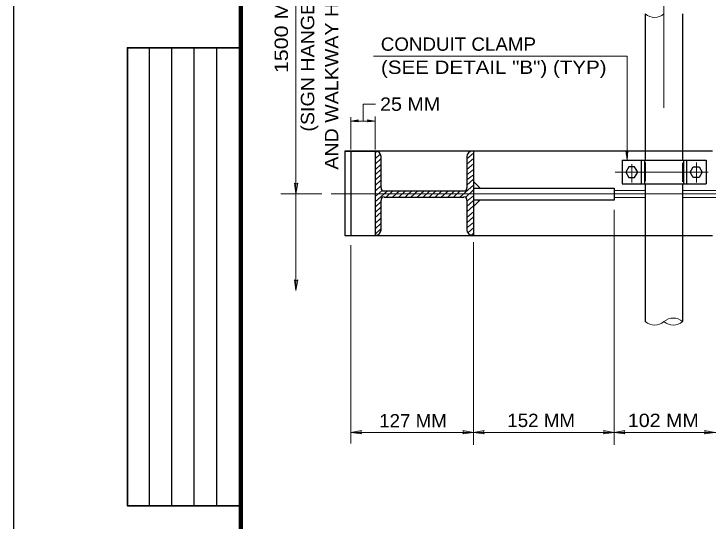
# Model space of a CAD drawing. Extents: x 312601.858 to 312602.699, y 144420.109 to 144420.704.
# Drawn here: x 312601.8578 to 312602.0138, y 144420.2326 to 144420.3467 of the extents above; entities that cross this region are included whole.
import ezdxf
from ezdxf.enums import TextEntityAlignment as Align

# ---------------------------------------------------------------- set-up
doc = ezdxf.new("R2010")
doc.units = 0
doc.header["$LTSCALE"] = 0.0012
for name, pattern in [('DOT_DASHED', [7.7, 5, -1.2, 0.3, -1.2]), ('LONG_DASHED', [7.5, 6, -1.5]), ('MEDIUM_DASHED', [4.5, 3, -1.5])]:
    doc.linetypes.add(name, pattern=pattern)
for name, color, linetype, lineweight in [('1', 7, 'Continuous', 13), ('2', 7, 'Continuous', 13), ('39', 7, 'Continuous', 13), ('60', 7, 'Continuous', 25)]:
    doc.layers.add(name, color=color, linetype=linetype, lineweight=lineweight)

msp = doc.modelspace()

# ---------------------------------------------------------------- hatches: boundary and pattern name
at = {"layer": '39'}
for points in [[(312601.9351, 144420.3226), (312601.9352, 144420.3224), (312601.9335, 144420.3226), (312601.9352, 144420.3229)], [(312601.9375, 144420.3226), (312601.9373, 144420.3229), (312601.939, 144420.3226), (312601.9373, 144420.3224)], [(312601.9212, 144420.3084), (312601.9216, 144420.3086), (312601.9212, 144420.3062), (312601.9209, 144420.3086)], [(312601.9212, 144420.2867), (312601.9216, 144420.2869), (312601.9212, 144420.2845), (312601.9209, 144420.2869)], [(312601.9357, 144420.2526), (312601.9359, 144420.2523), (312601.9335, 144420.2526), (312601.9359, 144420.253)], [(312601.9589, 144420.2526), (312601.9587, 144420.253), (312601.9611, 144420.2526), (312601.9587, 144420.2523)], [(312601.9633, 144420.2526), (312601.9635, 144420.2523), (312601.9611, 144420.2526), (312601.9635, 144420.253)], [(312601.9905, 144420.2526), (312601.9903, 144420.253), (312601.9927, 144420.2526), (312601.9903, 144420.2523)], [(312601.9949, 144420.2526), (312601.9951, 144420.2523), (312601.9927, 144420.2526), (312601.9951, 144420.253)], [(312602.0132, 144420.2526), (312602.013, 144420.253), (312602.0154, 144420.2526), (312602.013, 144420.2523)]]:
    msp.add_hatch(color=256, dxfattribs=at).paths.add_polyline_path(points)

# ---------------------------------------------------------------- linework, layer by layer
at = {"layer": '1', "linetype": 'DOT_DASHED'}
for p, q in [((312602.0039, 144420.4256), (312602.0039, 144420.2754)), ((312602.0112, 144420.3133), (312602.0112, 144420.3088)), ((312601.9967, 144420.3129), (312601.9967, 144420.3088)), ((312601.9929, 144420.3111), (312602.0138, 144420.3111)), ((312601.9291, 144420.3062), (312602.114, 144420.3062))]:
    msp.add_line(p, q, dxfattribs=at)
at = {"layer": '1', "lineweight": 25}
for p, q in [((312601.9997, 144420.3467), (312601.9997, 144420.3138)), ((312602.0081, 144420.3467), (312602.0081, 144420.3138)), ((312601.9322, 144420.3158), (312601.9322, 144420.2969)), ((312601.9322, 144420.3158), (312601.9391, 144420.3158)), ((312601.9997, 144420.3158), (312601.9322, 144420.3158)), ((312601.9335, 144420.3158), (312601.9335, 144420.2969)), ((312601.939, 144420.3158), (312601.939, 144420.2969)), ((312601.9611, 144420.3158), (312601.9611, 144420.2969)), ((312602.0148, 144420.3158), (312602.0081, 144420.3158)), ((312601.9403, 144420.3146), (312601.9403, 144420.3076)), ((312601.9596, 144420.3146), (312601.9596, 144420.3076)), ((312601.9945, 144420.3138), (312602.0134, 144420.3138)), ((312601.9988, 144420.3138), (312601.9988, 144420.3085)), ((312601.9995, 144420.3138), (312601.9995, 144420.3085)), ((312602.0083, 144420.3138), (312602.0083, 144420.3085)), ((312602.009, 144420.3138), (312602.009, 144420.3085)), ((312602.0134, 144420.3138), (312602.0134, 144420.3085)), ((312601.9997, 144420.3085), (312601.9997, 144420.2775)), ((312602.0081, 144420.3085), (312602.0081, 144420.2775)), ((312601.941, 144420.3069), (312601.9589, 144420.3069)), ((312601.9611, 144420.3075), (312601.9927, 144420.3075)), ((312601.9927, 144420.3075), (312601.9927, 144420.3048)), ((312601.941, 144420.3055), (312601.9589, 144420.3055)), ((312601.9403, 144420.3048), (312601.9403, 144420.2981)), ((312601.9596, 144420.3048), (312601.9596, 144420.2981)), ((312601.9611, 144420.3049), (312601.9927, 144420.3049)), ((312601.9322, 144420.2969), (312601.9391, 144420.2969)), ((312601.939, 144420.2969), (312601.9997, 144420.2969)), ((312602.0081, 144420.2969), (312602.0148, 144420.2969))]:
    msp.add_line(p, q, dxfattribs=at)
at = {"layer": '1'}
for p, q in [((312601.9335, 144420.3235), (312601.9335, 144420.3162)), ((312601.9335, 144420.3226), (312601.939, 144420.3226)), ((312601.939, 144420.3236), (312601.939, 144420.3162)), ((312601.939, 144420.3154), (312601.9394, 144420.3158)), ((312601.939, 144420.3141), (312601.9402, 144420.3152)), ((312601.9596, 144420.3141), (312601.9611, 144420.3154)), ((312601.939, 144420.3129), (312601.9403, 144420.3141)), ((312601.9596, 144420.3129), (312601.9611, 144420.3142)), ((312601.939, 144420.3116), (312601.9403, 144420.3128)), ((312601.939, 144420.3105), (312601.9403, 144420.3117)), ((312601.9596, 144420.3117), (312601.9611, 144420.313)), ((312601.9596, 144420.3105), (312601.9611, 144420.3117)), ((312601.939, 144420.3093), (312601.9403, 144420.3105)), ((312601.9596, 144420.3094), (312601.9611, 144420.3105)), ((312601.939, 144420.3081), (312601.9403, 144420.3093)), ((312601.9596, 144420.3082), (312601.9611, 144420.3095)), ((312601.939, 144420.3068), (312601.9403, 144420.308)), ((312601.939, 144420.3056), (312601.9406, 144420.307)), ((312601.939, 144420.3044), (312601.9418, 144420.3069)), ((312601.9415, 144420.3067), (312601.9417, 144420.3069)), ((312601.9415, 144420.3055), (312601.943, 144420.3069)), ((312601.9429, 144420.3055), (312601.9445, 144420.3069)), ((312601.9443, 144420.3055), (312601.9458, 144420.3069)), ((312601.9457, 144420.3055), (312601.9472, 144420.3069)), ((312601.947, 144420.3055), (312601.9486, 144420.3069)), ((312601.9484, 144420.3055), (312601.95, 144420.3069)), ((312601.9498, 144420.3055), (312601.9513, 144420.3069)), ((312601.9511, 144420.3055), (312601.9526, 144420.3069)), ((312601.9525, 144420.3055), (312601.954, 144420.3069)), ((312601.9538, 144420.3055), (312601.9555, 144420.3069)), ((312601.9553, 144420.3055), (312601.9568, 144420.3069)), ((312601.9566, 144420.3055), (312601.9581, 144420.3069)), ((312601.958, 144420.3055), (312601.9611, 144420.3082)), ((312601.9593, 144420.3054), (312601.9611, 144420.3071)), ((312601.9178, 144420.3062), (312601.927, 144420.3062)), ((312601.9212, 144420.3062), (312601.9212, 144420.2845)), ((312601.9457, 144420.3055), (312601.9466, 144420.3064)), ((312601.9596, 144420.3046), (312601.9611, 144420.3058)), ((312601.939, 144420.3032), (312601.9403, 144420.3044)), ((312601.9596, 144420.3034), (312601.9611, 144420.3047)), ((312601.939, 144420.302), (312601.9403, 144420.3032)), ((312601.9596, 144420.3022), (312601.9611, 144420.3035)), ((312601.9927, 144420.3026), (312601.9927, 144420.2498)), ((312601.939, 144420.3009), (312601.9403, 144420.302)), ((312601.939, 144420.2996), (312601.9403, 144420.3008)), ((312601.9596, 144420.3009), (312601.9611, 144420.3022)), ((312601.9596, 144420.2997), (312601.9611, 144420.3011)), ((312601.939, 144420.2984), (312601.9403, 144420.2996)), ((312601.9596, 144420.2986), (312601.9611, 144420.2998)), ((312601.939, 144420.2972), (312601.9403, 144420.2984)), ((312601.9598, 144420.2975), (312601.9611, 144420.2986)), ((312601.9606, 144420.2969), (312601.9611, 144420.2974)), ((312601.9335, 144420.2947), (312601.9335, 144420.2501)), ((312601.9611, 144420.2954), (312601.9611, 144420.2498))]:
    msp.add_line(p, q, dxfattribs=at)
at = {"layer": '1', "linetype": 'LONG_DASHED', "lineweight": 25}
for p, q in [((312602.0081, 144420.3158), (312601.9997, 144420.3158)), ((312601.9997, 144420.2969), (312602.0081, 144420.2969))]:
    msp.add_line(p, q, dxfattribs=at)
at = {"layer": '1', "linetype": 'MEDIUM_DASHED', "lineweight": 25}
for p, q in [((312601.9997, 144420.3133), (312601.9997, 144420.3091)), ((312602.0081, 144420.3132), (312602.0081, 144420.3089))]:
    msp.add_line(p, q, dxfattribs=at)
at = {"layer": '1', "linetype": 'LONG_DASHED'}
for p, q in [((312601.9927, 144420.307), (312601.9997, 144420.307)), ((312602.0081, 144420.307), (312602.042, 144420.307)), ((312601.9927, 144420.3054), (312601.9997, 144420.3054)), ((312602.0081, 144420.3054), (312602.042, 144420.3054))]:
    msp.add_line(p, q, dxfattribs=at)
at = {"layer": '1'}
for points in [[(312601.9212, 144420.4129), (312601.9212, 144420.3925), (312601.9212, 144420.3062)], [(312601.9386, 144420.3372), (312601.9956, 144420.3372), (312601.9956, 144420.3139)], [(312601.9335, 144420.2526), (312601.9611, 144420.2526), (312601.9927, 144420.2526), (312602.0154, 144420.2526), (312602.0985, 144420.2526)]]:
    msp.add_lwpolyline(points, dxfattribs=at)
msp.add_lwpolyline([(312601.9958, 144420.3159), (312601.9956, 144420.3139), (312601.9953, 144420.3159), (312601.9956, 144420.3156)], close=True, dxfattribs=at)
at = {"layer": '1', "lineweight": 25}
msp.add_lwpolyline([(312601.9945, 144420.3138), (312601.9945, 144420.3085), (312602.0134, 144420.3085)], dxfattribs=at)
for points in [[(312601.996, 144420.3099), (312601.9973, 144420.3099), (312601.998, 144420.3111), (312601.9973, 144420.3123), (312601.996, 144420.3123), (312601.9953, 144420.3111)], [(312602.0118, 144420.3099), (312602.0105, 144420.3099), (312602.0098, 144420.3111), (312602.0105, 144420.3123), (312602.0118, 144420.3123), (312602.0125, 144420.3111)]]:
    msp.add_lwpolyline(points, close=True, dxfattribs=at)
at = {"layer": '1'}
for centre, radius, start, end in [((312602.0018, 144420.349056), 0.003156, 228.29108, 311.70892), ((312602.0018, 144420.349056), 0.003156, 228.29108, 311.70892), ((312602.0018, 144420.349056), 0.003156, 228.29108, 311.70892), ((312601.958935, 144420.307565), 0.00068, 359.62724, 0), ((312602.0018, 144420.279856), 0.003156, 228.29108, 311.70892), ((312602.0018, 144420.279856), 0.003156, 228.29108, 311.70892), ((312602.0018, 144420.279856), 0.003156, 228.29108, 311.70892), ((312602.006, 144420.275144), 0.003156, 48.29108, 131.70892), ((312602.006, 144420.275144), 0.003156, 48.29108, 131.70892), ((312602.006, 144420.275144), 0.003156, 48.29108, 131.70892), ((312602.006, 144420.279856), 0.003156, 228.29108, 311.70892), ((312602.006, 144420.279856), 0.003156, 228.29108, 311.70892), ((312602.006, 144420.279856), 0.003156, 228.29108, 311.70892)]:
    msp.add_arc(centre, radius, start, end, dxfattribs=at)
at = {"layer": '1', "lineweight": 25}
for centre, radius, start, end in [((312601.93913, 144420.31462), 0.00119, 0, 90), ((312601.960805, 144420.31462), 0.00119, 90, 180), ((312601.941, 144420.307565), 0.00068, 180, 270), ((312601.958935, 144420.307565), 0.00068, 270, 0), ((312601.941, 144420.304845), 0.00068, 90, 180), ((312601.958935, 144420.304845), 0.00068, 0, 90), ((312601.93913, 144420.29813), 0.00119, 270, 0), ((312601.960805, 144420.29813), 0.00119, 180, 270)]:
    msp.add_arc(centre, radius, start, end, dxfattribs=at)
at = {"layer": '2'}
for p in [(312601.9363, 144420.3226), (312601.9391, 144420.3264)]:
    msp.add_line(p, (312601.9363, 144420.3264), dxfattribs=at)
for points in [[(312601.9611, 144420.3075), (312601.9626, 144420.3075), (312601.9611, 144420.309)], [(312601.9611, 144420.3049), (312601.9626, 144420.3049), (312601.9611, 144420.3034)]]:
    msp.add_lwpolyline(points, close=True, dxfattribs=at)
at = {"layer": '39', "lineweight": 25}
msp.add_line((312601.8578, 144420.1095), (312601.8578, 144420.7035), dxfattribs=at)
at = {"layer": '39', "lineweight": 158}
msp.add_lwpolyline([(312601.9088, 144420.1247), (312601.9088, 144420.6645), (312602.6838, 144420.6645)], dxfattribs=at)
at = {"layer": '39'}
for points in [[(312601.9351, 144420.3226), (312601.9352, 144420.3224), (312601.9335, 144420.3226), (312601.9352, 144420.3229)], [(312601.9375, 144420.3226), (312601.9373, 144420.3229), (312601.939, 144420.3226), (312601.9373, 144420.3224)], [(312601.9212, 144420.3084), (312601.9216, 144420.3086), (312601.9212, 144420.3062), (312601.9209, 144420.3086)], [(312601.9212, 144420.2867), (312601.9216, 144420.2869), (312601.9212, 144420.2845), (312601.9209, 144420.2869)], [(312601.9357, 144420.2526), (312601.9359, 144420.2523), (312601.9335, 144420.2526), (312601.9359, 144420.253)], [(312601.9589, 144420.2526), (312601.9587, 144420.253), (312601.9611, 144420.2526), (312601.9587, 144420.2523)], [(312601.9633, 144420.2526), (312601.9635, 144420.2523), (312601.9611, 144420.2526), (312601.9635, 144420.253)], [(312601.9905, 144420.2526), (312601.9903, 144420.253), (312601.9927, 144420.2526), (312601.9903, 144420.2523)], [(312601.9949, 144420.2526), (312601.9951, 144420.2523), (312601.9927, 144420.2526), (312601.9951, 144420.253)], [(312602.0132, 144420.2526), (312602.013, 144420.253), (312602.0154, 144420.2526), (312602.013, 144420.2523)]]:
    msp.add_lwpolyline(points, close=True, dxfattribs=at)
at = {"layer": '60'}
for p, q in [((312601.8883, 144420.2361), (312601.8883, 144420.3391)), ((312601.8933, 144420.2361), (312601.8933, 144420.3391)), ((312601.8983, 144420.2361), (312601.8983, 144420.3391)), ((312601.9034, 144420.2361), (312601.9034, 144420.3391))]:
    msp.add_line(p, q, dxfattribs=at)
at = {"layer": '60', "lineweight": 35}
msp.add_lwpolyline([(312601.9084, 144420.2361), (312601.8833, 144420.2361), (312601.8833, 144420.3391), (312601.9084, 144420.3391)], dxfattribs=at)

# ---------------------------------------------------------------- texts
at = {"layer": '2'}
for s, width, p in [('AND WALKWAY HANGER SPACING)', 1.1, (312601.9307, 144420.34955)), ('(SIGN HANGER, LUMINAIRE', 1.1, (312601.9253, 144420.34965)), ('1500 MM MAX', 1.2, (312601.9194, 144420.3493))]:
    msp.add_text(s, height=0.003, rotation=90, dxfattribs=dict(at, width=width)).set_placement(p, align=Align.CENTER)
for s, width, p in [('CONDUIT CLAMP', 1.05, (312601.9577, 144420.3384)), ('(SEE DETAIL "B") (TYP)', 1.15, (312601.96565, 144420.3332)), ('25 MM', 1.1, (312601.94685, 144420.3249)), ('127 MM', 1.05, (312601.9475, 144420.2537)), ('152 MM', 1.05, (312601.9763, 144420.2538)), ('102 MM', 1.1, (312602.00375, 144420.2538))]:
    msp.add_text(s, height=0.003, dxfattribs=dict(at, width=width)).set_placement(p, align=Align.CENTER)

doc.saveas('drawing.dxf')
